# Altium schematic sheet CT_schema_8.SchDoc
size 287 x 160 mm
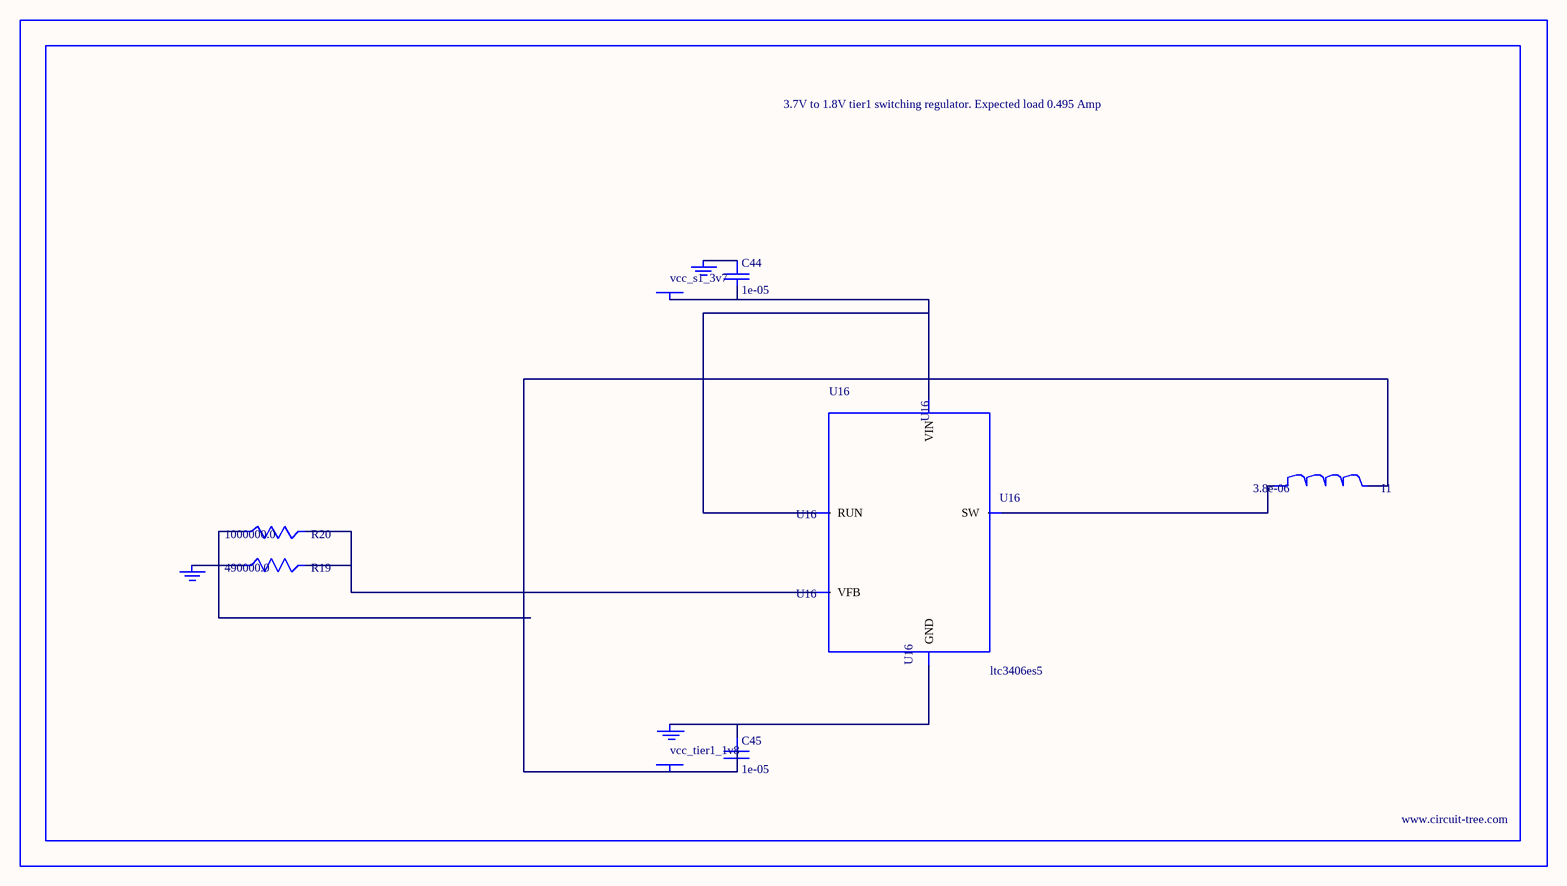
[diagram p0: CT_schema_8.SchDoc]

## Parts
BORDER7  (no value)
C44  1e-05  [C0805]
C45  1e-05  [C0805]
GND_INSTANCE_7_0  (no value)
GND_INSTANCE_7_1  (no value)
GND_INSTANCE_7_2  (no value)
I1  3.8e-06  [DR1040]
POWER_INSTANCE_7_0  vcc_tier1_1v8
POWER_INSTANCE_7_1  vcc_s1_3v7
R19  490000.0  [R0603]
R20  1000000.0  [R0603]
U16  ltc3406es5  [TSOT-23-5]

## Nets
NetC44_1: C44.1 GND_INSTANCE_7_1.0(GND)
NetC44_2: C44.2 POWER_INSTANCE_7_1.0(PWR) U16.1(RUN) U16.4(VIN)
NetC45_1: C45.1 GND_INSTANCE_7_0.0(GND) U16.2(GND)
NetC45_2: C45.2 I1.2 POWER_INSTANCE_7_0.0(PWR) R20.1
NetGND_INSTANCE_7_2_0: GND_INSTANCE_7_2.0(GND) R19.1
NetI1_1: I1.1 U16.3(SW)
NetR19_2: R19.2 R20.2 U16.5(VFB)

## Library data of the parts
BORDER7 = BORDER_PAGE7
C44 C45 = C0805C106K8RACTU
GND_INSTANCE_7_0-GND_INSTANCE_7_2 = GND
I1 = DR1040-3R8-R
POWER_INSTANCE_7_0 POWER_INSTANCE_7_1 = PWR
R19 = R19
R20 = RC0603JR-071ML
